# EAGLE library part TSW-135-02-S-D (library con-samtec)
THROUGH-HOLE .025" SQ POST HEADER Source: Samtec TSW.pdf
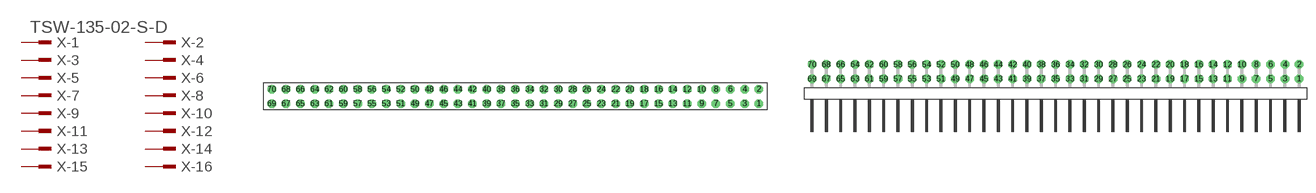
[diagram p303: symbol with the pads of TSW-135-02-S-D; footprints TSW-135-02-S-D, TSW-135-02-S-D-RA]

Designator prefix X; gates -1=MPINV -2=MPIN -3=MPIN -4=MPIN -5=MPIN -6=MPIN -7=MPIN -8=MPIN -9=MPIN -10=MPIN -11=MPIN -12=MPIN -13=MPIN -14=MPIN -15=MPIN -16=MPIN -17=MPIN -18=MPIN -19=MPIN -20=MPIN -21=MPIN -22=MPIN -23=MPIN -24=MPIN -25=MPIN -26=MPIN -27=MPIN -28=MPIN -29=MPIN -30=MPIN -31=MPIN -32=MPIN -33=MPIN -34=MPIN -35=MPIN -36=MPIN -37=MPIN -38=MPIN -39=MPIN -40=MPIN -41=MPIN -42=MPIN -43=MPIN -44=MPIN -45=MPIN -46=MPIN -47=MPIN -48=MPIN -49=MPIN -50=MPIN -51=MPIN -52=MPIN -53=MPIN -54=MPIN -55=MPIN -56=MPIN -57=MPIN -58=MPIN -59=MPIN -60=MPIN -61=MPIN -62=MPIN -63=MPIN -64=MPIN -65=MPIN -66=MPIN -67=MPIN -68=MPIN -69=MPIN -70=MPIN

## TSW-135-02-S-D (OC_FARNELL: unknown; OC_NEWARK: unknown)  [TSW-135-02-S-D]
1  -1:1  pas
2  -2:1  pas
3  -3:1  pas
4  -4:1  pas
5  -5:1  pas
6  -6:1  pas
7  -7:1  pas
8  -8:1  pas
9  -9:1  pas
10  -10:1  pas
11  -11:1  pas
12  -12:1  pas
13  -13:1  pas
14  -14:1  pas
15  -15:1  pas
16  -16:1  pas
17  -17:1  pas
18  -18:1  pas
19  -19:1  pas
20  -20:1  pas
21  -21:1  pas
22  -22:1  pas
23  -23:1  pas
24  -24:1  pas
25  -25:1  pas
26  -26:1  pas
27  -27:1  pas
28  -28:1  pas
29  -29:1  pas
30  -30:1  pas
31  -31:1  pas
32  -32:1  pas
33  -33:1  pas
34  -34:1  pas
35  -35:1  pas
36  -36:1  pas
37  -37:1  pas
38  -38:1  pas
39  -39:1  pas
40  -40:1  pas
41  -41:1  pas
42  -42:1  pas
43  -43:1  pas
44  -44:1  pas
45  -45:1  pas
46  -46:1  pas
47  -47:1  pas
48  -48:1  pas
49  -49:1  pas
50  -50:1  pas
51  -51:1  pas
52  -52:1  pas
53  -53:1  pas
54  -54:1  pas
55  -55:1  pas
56  -56:1  pas
57  -57:1  pas
58  -58:1  pas
59  -59:1  pas
60  -60:1  pas
61  -61:1  pas
62  -62:1  pas
63  -63:1  pas
64  -64:1  pas
65  -65:1  pas
66  -66:1  pas
67  -67:1  pas
68  -68:1  pas
69  -69:1  pas
70  -70:1  pas

## TSW-135-02-S-D-RA (OC_FARNELL: unknown; OC_NEWARK: unknown)  [TSW-135-02-S-D-RA]
Pads as for TSW-135-02-S-D

## Footprint TSW-135-02-S-D (pad centres in mm)
THROUGH-HOLE .025" SQ POST HEADER Source: Samtec TSW.pdf
drill 1 pad 1.5 octagon: 1 43.18,-1.27; 2 43.18,1.27; 3 40.64,-1.27; 4 40.64,1.27; 5 38.1,-1.27; 6 38.1,1.27; 7 35.56,-1.27; 8 35.56,1.27; 9 33.02,-1.27; 10 33.02,1.27; 11 30.48,-1.27; 12 30.48,1.27; 13 27.94,-1.27; 14 27.94,1.27; 15 25.4,-1.27; 16 25.4,1.27; 17 22.86,-1.27; 18 22.86,1.27; 19 20.32,-1.27; 20 20.32,1.27; 21 17.78,-1.27; 22 17.78,1.27; 23 15.24,-1.27; 24 15.24,1.27; 25 12.7,-1.27; 26 12.7,1.27; 27 10.16,-1.27; 28 10.16,1.27; 29 7.62,-1.27; 30 7.62,1.27; 31 5.08,-1.27; 32 5.08,1.27; 33 2.54,-1.27; 34 2.54,1.27; 35 0,-1.27; 36 0,1.27; 37 -2.54,-1.27; 38 -2.54,1.27; 39 -5.08,-1.27; 40 -5.08,1.27; 41 -7.62,-1.27; 42 -7.62,1.27; 43 -10.16,-1.27; 44 -10.16,1.27; 45 -12.7,-1.27; 46 -12.7,1.27; 47 -15.24,-1.27; 48 -15.24,1.27; 49 -17.78,-1.27; 50 -17.78,1.27; 51 -20.32,-1.27; 52 -20.32,1.27; 53 -22.86,-1.27; 54 -22.86,1.27; 55 -25.4,-1.27; 56 -25.4,1.27; 57 -27.94,-1.27; 58 -27.94,1.27; 59 -30.48,-1.27; 60 -30.48,1.27; 61 -33.02,-1.27; 62 -33.02,1.27; 63 -35.56,-1.27; 64 -35.56,1.27; 65 -38.1,-1.27; 66 -38.1,1.27; 67 -40.64,-1.27; 68 -40.64,1.27; 69 -43.18,-1.27; 70 -43.18,1.27

## Footprint TSW-135-02-S-D-RA (pad centres in mm)
THROUGH-HOLE .025" SQ POST HEADER Source: Samtec TSW.pdf
drill 1 pad 1.5 octagon: 1 43.18,1.524; 2 43.18,4.064; 3 40.64,1.524; 4 40.64,4.064; 5 38.1,1.524; 6 38.1,4.064; 7 35.56,1.524; 8 35.56,4.064; 9 33.02,1.524; 10 33.02,4.064; 11 30.48,1.524; 12 30.48,4.064; 13 27.94,1.524; 14 27.94,4.064; 15 25.4,1.524; 16 25.4,4.064; 17 22.86,1.524; 18 22.86,4.064; 19 20.32,1.524; 20 20.32,4.064; 21 17.78,1.524; 22 17.78,4.064; 23 15.24,1.524; 24 15.24,4.064; 25 12.7,1.524; 26 12.7,4.064; 27 10.16,1.524; 28 10.16,4.064; 29 7.62,1.524; 30 7.62,4.064; 31 5.08,1.524; 32 5.08,4.064; 33 2.54,1.524; 34 2.54,4.064; 35 0,1.524; 36 0,4.064; 37 -2.54,1.524; 38 -2.54,4.064; 39 -5.08,1.524; 40 -5.08,4.064; 41 -7.62,1.524; 42 -7.62,4.064; 43 -10.16,1.524; 44 -10.16,4.064; 45 -12.7,1.524; 46 -12.7,4.064; 47 -15.24,1.524; 48 -15.24,4.064; 49 -17.78,1.524; 50 -17.78,4.064; 51 -20.32,1.524; 52 -20.32,4.064; 53 -22.86,1.524; 54 -22.86,4.064; 55 -25.4,1.524; 56 -25.4,4.064; 57 -27.94,1.524; 58 -27.94,4.064; 59 -30.48,1.524; 60 -30.48,4.064; 61 -33.02,1.524; 62 -33.02,4.064; 63 -35.56,1.524; 64 -35.56,4.064; 65 -38.1,1.524; 66 -38.1,4.064; 67 -40.64,1.524; 68 -40.64,4.064; 69 -43.18,1.524; 70 -43.18,4.064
